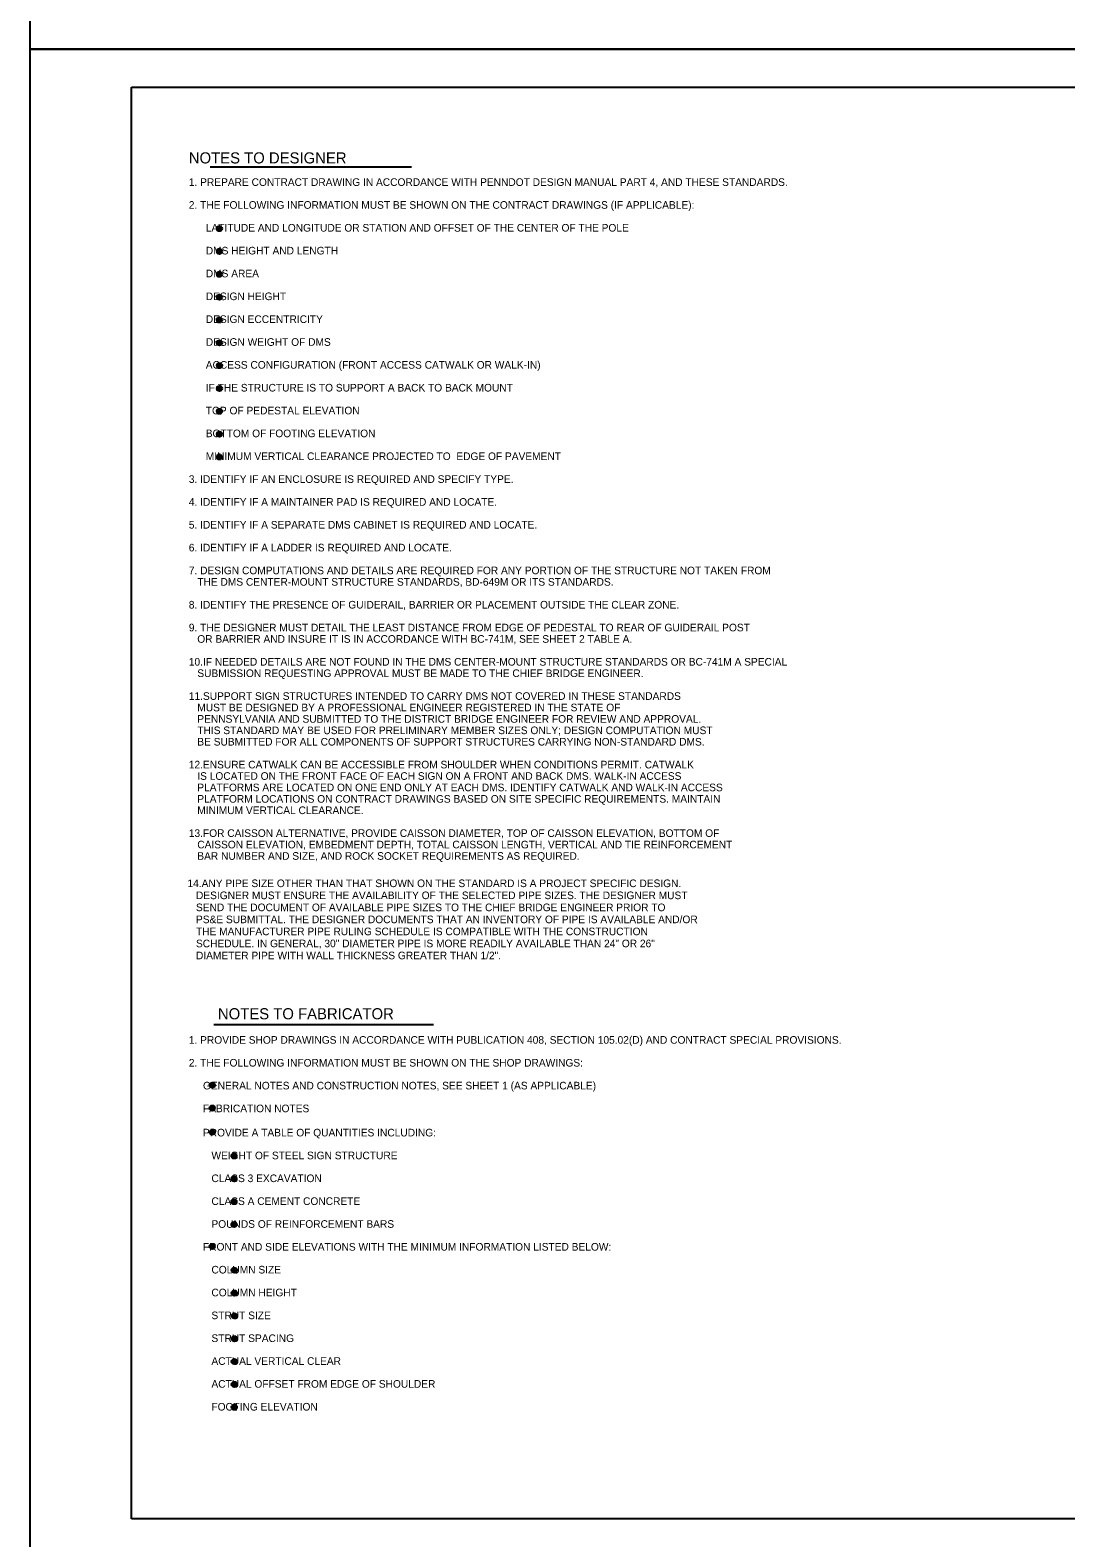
# Model space of a CAD drawing. Extents: x 3829340 to 3831660, y 499389 to 501171.
# Drawn here: x 3829340 to 3829748, y 499991 to 500585 of the extents above; entities that cross this region are included whole.
import ezdxf

# ---------------------------------------------------------------- set-up
doc = ezdxf.new("R2010")
doc.units = 0
for name, color, linetype in [('10', 7, 'Continuous'), ('2', 7, 'Continuous'), ('DIM TXT', 7, 'Continuous'), ('PLT-BNDY', 7, 'Continuous'), ('Pr_dimension_ln', 7, 'Continuous')]:
    doc.layers.add(name, color=color, linetype=linetype)

msp = doc.modelspace()

# ---------------------------------------------------------------- linework, layer by layer
at = {"layer": '2'}
for p, q in [((3829379.96, 499998.19), (3829379.96, 500562.19)), ((3829379.96, 500562.19), (3830165.96, 500562.19)), ((3830165.96, 499998.19), (3829379.96, 499998.19))]:
    msp.add_line(p, q, dxfattribs=at)
at = {"layer": 'DIM TXT'}
for centre, radius in [((3829414.57, 500506.51), 1.04), ((3829414.57, 500506.51), 0.783), ((3829414.57, 500506.51), 0.522), ((3829414.57, 500506.51), 0.261), ((3829414.57, 500506.51), 0.00000209), ((3829414.57, 500497.51), 1.04), ((3829414.57, 500497.51), 0.783), ((3829414.57, 500497.51), 0.522), ((3829414.57, 500497.51), 0.261), ((3829414.57, 500497.51), 0.00000209), ((3829414.57, 500488.51), 1.04), ((3829414.57, 500488.51), 0.783), ((3829414.57, 500488.51), 0.522), ((3829414.57, 500488.51), 0.261), ((3829414.57, 500488.51), 0.00000209), ((3829414.57, 500479.51), 1.04), ((3829414.57, 500479.51), 0.783), ((3829414.57, 500479.51), 0.522), ((3829414.57, 500479.51), 0.261), ((3829414.57, 500479.51), 0.00000209), ((3829414.57, 500470.51), 1.04), ((3829414.57, 500470.51), 0.783), ((3829414.57, 500470.51), 0.522), ((3829414.57, 500470.51), 0.261), ((3829414.57, 500470.51), 0.00000209), ((3829414.57, 500461.51), 1.04), ((3829414.57, 500461.51), 0.783), ((3829414.57, 500461.51), 0.522), ((3829414.57, 500461.51), 0.261), ((3829414.57, 500461.51), 0.00000209), ((3829414.57, 500452.51), 1.04), ((3829414.57, 500452.51), 0.783), ((3829414.57, 500452.51), 0.522), ((3829414.57, 500452.51), 0.261), ((3829414.57, 500452.51), 0.00000209), ((3829414.57, 500443.51), 1.04), ((3829414.57, 500443.51), 0.783), ((3829414.57, 500443.51), 0.522), ((3829414.57, 500443.51), 0.261), ((3829414.57, 500443.51), 0.00000209), ((3829414.57, 500434.51), 1.04), ((3829414.57, 500434.51), 0.783), ((3829414.57, 500434.51), 0.522), ((3829414.57, 500434.51), 0.261), ((3829414.57, 500434.51), 0.00000209), ((3829414.57, 500425.51), 1.04), ((3829414.57, 500425.51), 0.783), ((3829414.57, 500425.51), 0.522), ((3829414.57, 500425.51), 0.261), ((3829414.57, 500425.51), 0.00000209), ((3829414.57, 500416.51), 1.04), ((3829414.57, 500416.51), 0.783), ((3829414.57, 500416.51), 0.522), ((3829414.57, 500416.51), 0.261), ((3829414.57, 500416.51), 0.00000209), ((3829411.71, 500169.02), 1.04), ((3829411.71, 500169.02), 0.783), ((3829411.71, 500169.02), 0.522), ((3829411.71, 500169.02), 0.261), ((3829411.71, 500169.02), 0.00000209), ((3829411.71, 500160.02), 1.04), ((3829411.71, 500160.02), 0.783), ((3829411.71, 500160.02), 0.522), ((3829411.71, 500160.02), 0.261), ((3829411.71, 500160.02), 0.00000209), ((3829411.71, 500150.49), 1.04), ((3829411.71, 500150.49), 0.783), ((3829411.71, 500150.49), 0.522), ((3829411.71, 500150.49), 0.261), ((3829411.71, 500150.49), 0.00000209), ((3829420.3, 500141.14), 1.04), ((3829420.3, 500141.14), 0.783), ((3829420.3, 500141.14), 0.522), ((3829420.3, 500141.14), 0.261), ((3829420.3, 500141.14), 0.00000209), ((3829420.3, 500132.14), 1.04), ((3829420.3, 500132.14), 0.783), ((3829420.3, 500132.14), 0.522), ((3829420.3, 500132.14), 0.261), ((3829420.3, 500132.14), 0.00000209), ((3829420.3, 500123.14), 1.04), ((3829420.3, 500123.14), 0.783), ((3829420.3, 500123.14), 0.522), ((3829420.3, 500123.14), 0.261), ((3829420.3, 500123.14), 0.00000209), ((3829420.3, 500114.14), 1.04), ((3829420.3, 500114.14), 0.783), ((3829420.3, 500114.14), 0.522), ((3829420.3, 500114.14), 0.261), ((3829420.3, 500114.14), 0.00000209), ((3829411.71, 500105.5), 1.04), ((3829411.71, 500105.5), 0.783), ((3829411.71, 500105.5), 0.522), ((3829411.71, 500105.5), 0.261), ((3829411.71, 500105.5), 0.00000209), ((3829420.4, 500096.14), 1.04), ((3829420.4, 500096.14), 0.783), ((3829420.4, 500096.14), 0.522), ((3829420.4, 500096.14), 0.261), ((3829420.4, 500096.14), 0.00000209), ((3829420.4, 500087.14), 1.04), ((3829420.4, 500087.14), 0.783), ((3829420.4, 500087.14), 0.522), ((3829420.4, 500087.14), 0.261), ((3829420.4, 500087.14), 0.00000209), ((3829420.4, 500078.14), 1.04), ((3829420.4, 500078.14), 0.783), ((3829420.4, 500078.14), 0.522), ((3829420.4, 500078.14), 0.261), ((3829420.4, 500078.14), 0.00000209), ((3829420.4, 500069.14), 1.04), ((3829420.4, 500069.14), 0.783), ((3829420.4, 500069.14), 0.522), ((3829420.4, 500069.14), 0.261), ((3829420.4, 500069.14), 0.00000209), ((3829420.4, 500060.14), 1.04), ((3829420.4, 500060.14), 0.783), ((3829420.4, 500060.14), 0.522), ((3829420.4, 500060.14), 0.261), ((3829420.4, 500060.14), 0.00000209), ((3829420.4, 500051.14), 1.04), ((3829420.4, 500051.14), 0.783), ((3829420.4, 500051.14), 0.522), ((3829420.4, 500051.14), 0.261), ((3829420.4, 500051.14), 0.00000209), ((3829420.4, 500042.14), 1.04), ((3829420.4, 500042.14), 0.783), ((3829420.4, 500042.14), 0.522), ((3829420.4, 500042.14), 0.261), ((3829420.4, 500042.14), 0.00000209)]:
    msp.add_circle(centre, radius, dxfattribs=at)
at = {"layer": 'PLT-BNDY'}
for points in [[(3829339.96, 501171.19), (3830180.96, 501171.19), (3830180.96, 500577.19), (3829339.96, 500577.19)], [(3829339.96, 500577.19), (3830180.96, 500577.19), (3830180.96, 499983.19), (3829339.96, 499983.19)]]:
    msp.add_lwpolyline(points, close=True, dxfattribs=at)
at = {"layer": 'Pr_dimension_ln'}
for p, q in [((3829410.96, 500530.79), (3829490.25, 500530.79)), ((3829412.29, 500192.92), (3829498.93, 500192.92))]:
    msp.add_line(p, q, dxfattribs=at)

# ---------------------------------------------------------------- texts
at = {"layer": '10'}
for s, p in [('14.ANY PIPE SIZE OTHER THAN THAT SHOWN ON THE STANDARD IS A PROJECT SPECIFIC DESIGN.', (3829401.97, 500247.06)), ('   DESIGNER MUST ENSURE THE AVAILABILITY OF THE SELECTED PIPE SIZES. THE DESIGNER MUST', (3829401.97, 500242.32)), ('   SEND THE DOCUMENT OF AVAILABLE PIPE SIZES TO THE CHIEF BRIDGE ENGINEER PRIOR TO', (3829401.97, 500237.58)), ('   PS&E SUBMITTAL. THE DESIGNER DOCUMENTS THAT AN INVENTORY OF PIPE IS AVAILABLE AND/OR', (3829401.97, 500232.84)), ('   THE MANUFACTURER PIPE RULING SCHEDULE IS COMPATIBLE WITH THE CONSTRUCTION', (3829401.97, 500228.1)), ('   SCHEDULE. IN GENERAL, 30" DIAMETER PIPE IS MORE READILY AVAILABLE THAN 24" OR 26"', (3829401.97, 500223.36)), ('   DIAMETER PIPE WITH WALL THICKNESS GREATER THAN 1/2".', (3829401.97, 500218.62))]:
    msp.add_text(s, height=3, dxfattribs=at).set_placement(p)
at = {"layer": 'Pr_dimension_ln'}
for s, height, p in [('    NOTES TO DESIGNER', 4.3799, (3829395.99, 500532.17)), ('1. PREPARE CONTRACT DRAWING IN ACCORDANCE WITH PENNDOT DESIGN MANUAL PART 4, AND THESE STANDARDS.', 2.9999, (3829402.49, 500523.32)), ('2. THE FOLLOWING INFORMATION MUST BE SHOWN ON THE CONTRACT DRAWINGS (IF APPLICABLE):', 2.9999, (3829402.49, 500514.32)), ('      LATITUDE AND LONGITUDE OR STATION AND OFFSET OF THE CENTER OF THE POLE', 2.9999, (3829402.49, 500505.32)), ('      DMS HEIGHT AND LENGTH', 2.9999, (3829402.49, 500496.32)), ('      DMS AREA', 2.9999, (3829402.49, 500487.32)), ('      DESIGN HEIGHT', 2.9999, (3829402.49, 500478.32)), ('      DESIGN ECCENTRICITY', 2.9999, (3829402.49, 500469.32)), ('      DESIGN WEIGHT OF DMS', 2.9999, (3829402.49, 500460.32)), ('      ACCESS CONFIGURATION (FRONT ACCESS CATWALK OR WALK-IN)', 2.9999, (3829402.49, 500451.32)), ('      IF THE STRUCTURE IS TO SUPPORT A BACK TO BACK MOUNT', 2.9999, (3829402.49, 500442.32)), ('      TOP OF PEDESTAL ELEVATION', 2.9999, (3829402.49, 500433.32)), ('      BOTTOM OF FOOTING ELEVATION', 2.9999, (3829402.49, 500424.32)), ('      MINIMUM VERTICAL CLEARANCE PROJECTED TO  EDGE OF PAVEMENT', 2.9999, (3829402.49, 500415.32)), ('3. IDENTIFY IF AN ENCLOSURE IS REQUIRED AND SPECIFY TYPE.', 2.9999, (3829402.49, 500406.32)), ('4. IDENTIFY IF A MAINTAINER PAD IS REQUIRED AND LOCATE.', 2.9999, (3829402.49, 500397.32)), ('5. IDENTIFY IF A SEPARATE DMS CABINET IS REQUIRED AND LOCATE.', 2.9999, (3829402.49, 500388.32)), ('6. IDENTIFY IF A LADDER IS REQUIRED AND LOCATE.', 2.9999, (3829402.49, 500379.32)), ('7. DESIGN COMPUTATIONS AND DETAILS ARE REQUIRED FOR ANY PORTION OF THE STRUCTURE NOT TAKEN FROM', 2.9999, (3829402.49, 500370.32)), ('   THE DMS CENTER-MOUNT STRUCTURE STANDARDS, BD-649M OR ITS STANDARDS.', 2.9999, (3829402.49, 500365.82)), ('8. IDENTIFY THE PRESENCE OF GUIDERAIL, BARRIER OR PLACEMENT OUTSIDE THE CLEAR ZONE.', 2.9999, (3829402.49, 500356.82)), ('9. THE DESIGNER MUST DETAIL THE LEAST DISTANCE FROM EDGE OF PEDESTAL TO REAR OF GUIDERAIL POST', 2.9999, (3829402.49, 500347.83)), ('   OR BARRIER AND INSURE IT IS IN ACCORDANCE WITH BC-741M, SEE SHEET 2 TABLE A.', 2.9999, (3829402.49, 500343.33)), ('10.IF NEEDED DETAILS ARE NOT FOUND IN THE DMS CENTER-MOUNT STRUCTURE STANDARDS OR BC-741M A SPECIAL', 2.9999, (3829402.49, 500334.33)), ('   SUBMISSION REQUESTING APPROVAL MUST BE MADE TO THE CHIEF BRIDGE ENGINEER.', 2.9999, (3829402.49, 500329.83)), ('11.SUPPORT SIGN STRUCTURES INTENDED TO CARRY DMS NOT COVERED IN THESE STANDARDS ', 2.9999, (3829402.49, 500320.83)), ('   MUST BE DESIGNED BY A PROFESSIONAL ENGINEER REGISTERED IN THE STATE OF ', 2.9999, (3829402.49, 500316.33)), ('   PENNSYLVANIA AND SUBMITTED TO THE DISTRICT BRIDGE ENGINEER FOR REVIEW AND APPROVAL.', 2.9999, (3829402.49, 500311.83)), ('   THIS STANDARD MAY BE USED FOR PRELIMINARY MEMBER SIZES ONLY; DESIGN COMPUTATION MUST ', 2.9999, (3829402.49, 500307.33)), ('   BE SUBMITTED FOR ALL COMPONENTS OF SUPPORT STRUCTURES CARRYING NON-STANDARD DMS.', 2.9999, (3829402.49, 500302.83)), ('12.ENSURE CATWALK CAN BE ACCESSIBLE FROM SHOULDER WHEN CONDITIONS PERMIT. CATWALK', 2.9999, (3829402.49, 500293.83)), ('   IS LOCATED ON THE FRONT FACE OF EACH SIGN ON A FRONT AND BACK DMS. WALK-IN ACCESS', 2.9999, (3829402.49, 500289.33)), ('   PLATFORMS ARE LOCATED ON ONE END ONLY AT EACH DMS. IDENTIFY CATWALK AND WALK-IN ACCESS', 2.9999, (3829402.49, 500284.83)), ('   PLATFORM LOCATIONS ON CONTRACT DRAWINGS BASED ON SITE SPECIFIC REQUIREMENTS. MAINTAIN', 2.9999, (3829402.49, 500280.33)), ('   MINIMUM VERTICAL CLEARANCE.', 2.9999, (3829402.49, 500275.83)), ('13.FOR CAISSON ALTERNATIVE, PROVIDE CAISSON DIAMETER, TOP OF CAISSON ELEVATION, BOTTOM OF', 2.9999, (3829402.49, 500266.83)), ('   CAISSON ELEVATION, EMBEDMENT DEPTH, TOTAL CAISSON LENGTH, VERTICAL AND TIE REINFORCEMENT', 2.9999, (3829402.49, 500262.33)), ('   BAR NUMBER AND SIZE, AND ROCK SOCKET REQUIREMENTS AS REQUIRED.', 2.9999, (3829402.49, 500257.83)), ('NOTES TO FABRICATOR', 4.3799, (3829413.97, 500194.98)), ('1. PROVIDE SHOP DRAWINGS IN ACCORDANCE WITH PUBLICATION 408, SECTION 105.02(D) AND CONTRACT SPECIAL PROVISIONS.', 2.99992, (3829402.49, 500185.36)), ('2. THE FOLLOWING INFORMATION MUST BE SHOWN ON THE SHOP DRAWINGS:', 2.9999, (3829402.49, 500176.36)), ('     GENERAL NOTES AND CONSTRUCTION NOTES, SEE SHEET 1 (AS APPLICABLE)', 2.9999, (3829402.49, 500167.36)), ('     FABRICATION NOTES', 2.9999, (3829402.49, 500158.36)), ('     PROVIDE A TABLE OF QUANTITIES INCLUDING:', 2.9999, (3829402.49, 500148.84)), ('        WEIGHT OF STEEL SIGN STRUCTURE', 2.9999, (3829402.49, 500139.84)), ('        CLASS 3 EXCAVATION', 2.9999, (3829402.49, 500130.84)), ('        CLASS A CEMENT CONCRETE', 2.9999, (3829402.49, 500121.84)), ('        POUNDS OF REINFORCEMENT BARS', 2.9999, (3829402.49, 500112.84)), ('     FRONT AND SIDE ELEVATIONS WITH THE MINIMUM INFORMATION LISTED BELOW:', 2.9999, (3829402.49, 500103.84)), ('        COLUMN SIZE', 2.9999, (3829402.49, 500094.84)), ('        COLUMN HEIGHT', 2.9999, (3829402.49, 500085.84)), ('        STRUT SIZE', 2.9999, (3829402.49, 500076.84)), ('        STRUT SPACING', 2.9999, (3829402.49, 500067.84)), ('        ACTUAL VERTICAL CLEAR', 2.9999, (3829402.49, 500058.84)), ('        ACTUAL OFFSET FROM EDGE OF SHOULDER', 2.9999, (3829402.49, 500049.84)), ('        FOOTING ELEVATION', 2.9999, (3829402.49, 500040.84))]:
    msp.add_text(s, height=height, rotation=360, dxfattribs=at).set_placement(p)

doc.saveas('drawing.dxf')
